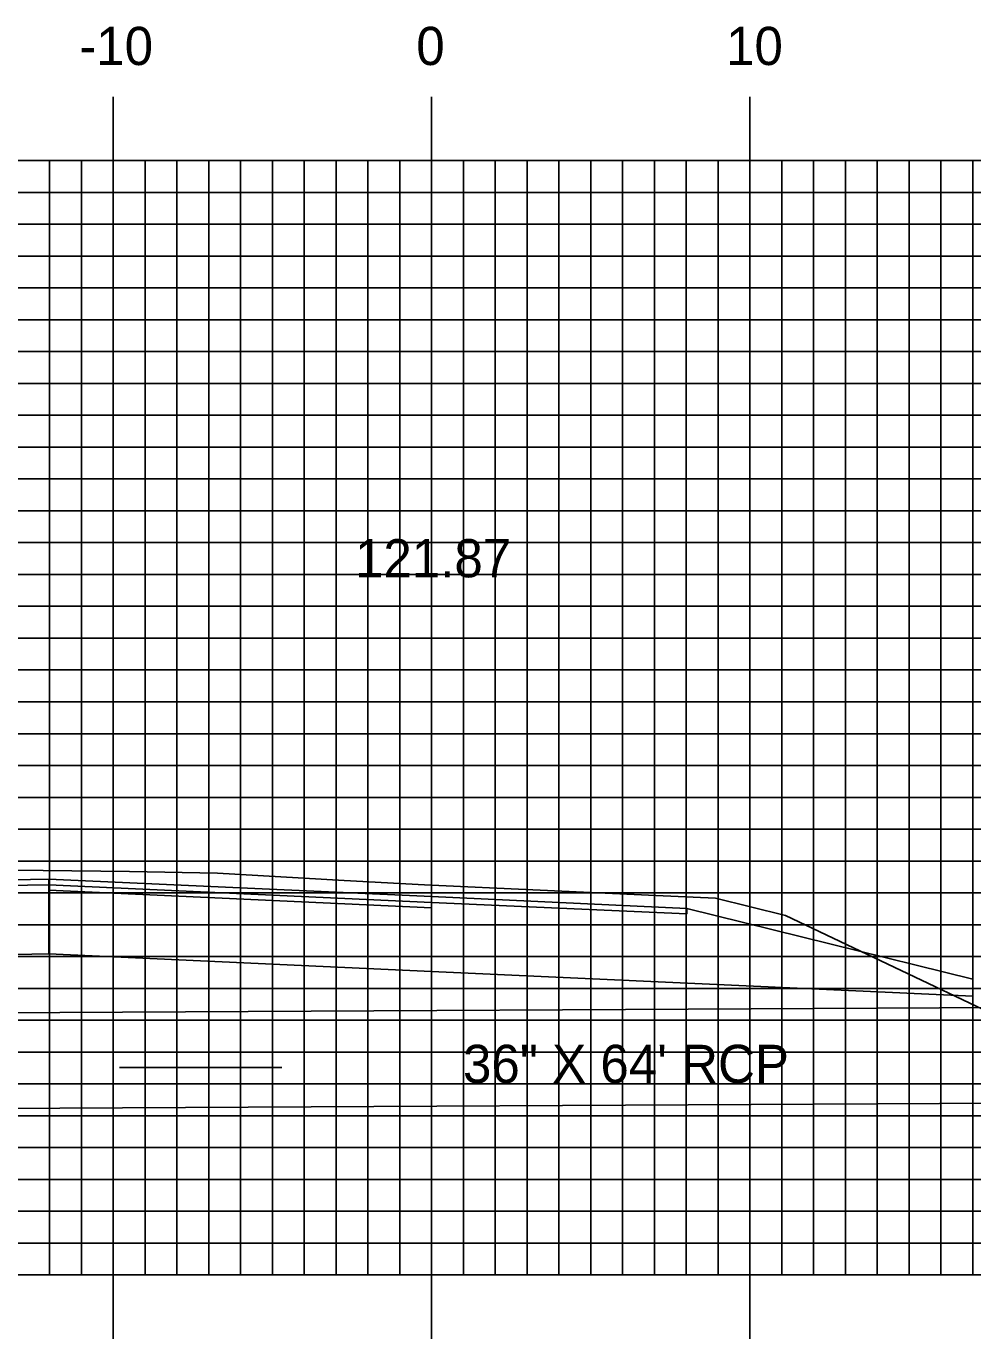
# Model space of a CAD drawing. Extents: x 853328 to 853671, y 364661 to 364881.
# Drawn here: x 853480.56 to 853510.3, y 364684.37 to 364725.59 of the extents above; entities that cross this region are included whole.
import ezdxf

# ---------------------------------------------------------------- set-up
doc = ezdxf.new("R2010")
doc.units = 0
for name, color, linetype in [('D_Drainage_Culvert', 7, 'Continuous'), ('D_Drainage_Text', 7, 'Continuous'), ('D_Roadway_Centerline_Text', 7, 'Continuous'), ('D_Roadway_Edge_Shoulder', 7, 'Continuous'), ('D_Roadway_Edge_TW', 7, 'Continuous'), ('D_Roadway_Pavement', 7, 'Continuous'), ('D_Roadway_SlopeLines', 7, 'Continuous'), ('D_Roadway_SubGrade', 7, 'Continuous'), ('H_V ANNOTATION', 7, 'Continuous'), ('MAJOR', 7, 'Continuous'), ('MINOR', 7, 'Continuous'), ('S_Roadway_Centerline', 7, 'Continuous')]:
    doc.layers.add(name, color=color, linetype=linetype)

msp = doc.modelspace()

# ---------------------------------------------------------------- linework, layer by layer
at = {"layer": 'D_Drainage_Culvert'}
for p, q in [((853457.848, 364694.502), (853517.997, 364694.803)), ((853488.593, 364692.893), (853483.484, 364692.893)), ((853457.863, 364691.494), (853517.992, 364691.803))]:
    msp.add_line(p, q, dxfattribs=at)
at = {"layer": 'D_Roadway_Edge_Shoulder'}
for points in [[(853481.266, 364698.809), (853477.256, 364698.73), (853477.256, 364698.564), (853481.266, 364698.63)], [(853493.294, 364698.255), (853501.313, 364697.886), (853501.313, 364697.719), (853493.294, 364698.075)]]:
    msp.add_lwpolyline(points, close=True, dxfattribs=at)
at = {"layer": 'D_Roadway_Edge_TW'}
msp.add_lwpolyline([(853481.266, 364698.809), (853493.294, 364698.255), (853493.294, 364698.075), (853481.266, 364698.63)], close=True, dxfattribs=at)
at = {"layer": 'D_Roadway_Pavement'}
msp.add_lwpolyline([(853481.266, 364698.63), (853493.294, 364698.075), (853493.294, 364697.909), (853481.266, 364698.463)], close=True, dxfattribs=at)
for points in [[(853481.266, 364698.63), (853481.266, 364698.463)], [(853493.294, 364698.075), (853493.294, 364697.909)], [(853493.294, 364698.075), (853493.294, 364697.909)]]:
    msp.add_lwpolyline(points, dxfattribs=at)
at = {"layer": 'D_Roadway_SlopeLines'}
msp.add_line((853501.313, 364697.886), (853510.296, 364695.661), dxfattribs=at)
at = {"layer": 'D_Roadway_SubGrade'}
for points in [[(853481.266, 364696.463), (853467.26, 364696.186), (853477.256, 364698.73), (853477.256, 364698.564), (853481.266, 364698.63), (853481.266, 364698.463)], [(853481.266, 364698.463), (853493.294, 364697.909), (853493.294, 364695.909), (853481.266, 364696.463)], [(853493.294, 364697.909), (853493.294, 364698.075), (853501.313, 364697.719), (853501.313, 364697.886), (853510.296, 364695.661), (853510.296, 364695.125), (853493.294, 364695.909)]]:
    msp.add_lwpolyline(points, close=True, dxfattribs=at)
at = {"layer": 'MAJOR'}
for p, q in [((853483.294, 364723.378), (853483.294, 364721.374)), ((853493.294, 364723.378), (853493.294, 364721.374)), ((853503.294, 364723.378), (853503.294, 364721.374)), ((853353.294, 364721.374), (853633.294, 364721.374)), ((853353.294, 364721.374), (853633.294, 364721.374)), ((853483.294, 364686.374), (853483.294, 364721.374)), ((853493.294, 364686.374), (853493.294, 364721.374)), ((853503.294, 364686.374), (853503.294, 364721.374)), ((853353.294, 364716.374), (853633.294, 364716.374)), ((853353.294, 364711.374), (853633.294, 364711.374)), ((853353.294, 364706.374), (853633.294, 364706.374)), ((853353.294, 364701.374), (853633.294, 364701.374)), ((853353.294, 364696.374), (853633.294, 364696.374)), ((853353.294, 364691.374), (853633.294, 364691.374)), ((853353.294, 364686.374), (853633.294, 364686.374)), ((853353.294, 364686.374), (853633.294, 364686.374)), ((853483.294, 364684.37), (853483.294, 364686.374)), ((853493.294, 364684.37), (853493.294, 364686.374)), ((853503.294, 364684.37), (853503.294, 364686.374))]:
    msp.add_line(p, q, dxfattribs=at)
at = {"layer": 'MINOR'}
for p, q in [((853481.294, 364686.374), (853481.294, 364721.374)), ((853482.294, 364686.374), (853482.294, 364721.374)), ((853484.294, 364686.374), (853484.294, 364721.374)), ((853485.294, 364686.374), (853485.294, 364721.374)), ((853486.294, 364686.374), (853486.294, 364721.374)), ((853487.294, 364686.374), (853487.294, 364721.374)), ((853488.294, 364686.374), (853488.294, 364721.374)), ((853489.294, 364686.374), (853489.294, 364721.374)), ((853490.294, 364686.374), (853490.294, 364721.374)), ((853491.294, 364686.374), (853491.294, 364721.374)), ((853492.294, 364686.374), (853492.294, 364721.374)), ((853494.294, 364686.374), (853494.294, 364721.374)), ((853495.294, 364686.374), (853495.294, 364721.374)), ((853496.294, 364686.374), (853496.294, 364721.374)), ((853497.294, 364686.374), (853497.294, 364721.374)), ((853498.294, 364686.374), (853498.294, 364721.374)), ((853499.294, 364686.374), (853499.294, 364721.374)), ((853500.294, 364686.374), (853500.294, 364721.374)), ((853501.294, 364686.374), (853501.294, 364721.374)), ((853502.294, 364686.374), (853502.294, 364721.374)), ((853504.294, 364686.374), (853504.294, 364721.374)), ((853505.294, 364686.374), (853505.294, 364721.374)), ((853506.294, 364686.374), (853506.294, 364721.374)), ((853507.294, 364686.374), (853507.294, 364721.374)), ((853508.294, 364686.374), (853508.294, 364721.374)), ((853509.294, 364686.374), (853509.294, 364721.374)), ((853510.294, 364686.374), (853510.294, 364721.374)), ((853353.294, 364720.374), (853633.294, 364720.374)), ((853353.294, 364719.374), (853633.294, 364719.374)), ((853353.294, 364718.374), (853633.294, 364718.374)), ((853353.294, 364717.374), (853633.294, 364717.374)), ((853353.294, 364715.374), (853633.294, 364715.374)), ((853353.294, 364714.374), (853633.294, 364714.374)), ((853353.294, 364713.374), (853633.294, 364713.374)), ((853353.294, 364712.374), (853633.294, 364712.374)), ((853353.294, 364710.374), (853633.294, 364710.374)), ((853353.294, 364709.374), (853633.294, 364709.374)), ((853353.294, 364708.374), (853633.294, 364708.374)), ((853353.294, 364707.374), (853633.294, 364707.374)), ((853353.294, 364705.374), (853633.294, 364705.374)), ((853353.294, 364704.374), (853633.294, 364704.374)), ((853353.294, 364703.374), (853633.294, 364703.374)), ((853353.294, 364702.374), (853633.294, 364702.374)), ((853353.294, 364700.374), (853633.294, 364700.374)), ((853353.294, 364699.374), (853633.294, 364699.374)), ((853353.294, 364698.374), (853633.294, 364698.374)), ((853353.294, 364697.374), (853633.294, 364697.374)), ((853353.294, 364695.374), (853633.294, 364695.374)), ((853353.294, 364694.374), (853633.294, 364694.374)), ((853353.294, 364693.374), (853633.294, 364693.374)), ((853353.294, 364692.374), (853633.294, 364692.374)), ((853353.294, 364690.374), (853633.294, 364690.374)), ((853353.294, 364689.374), (853633.294, 364689.374)), ((853353.294, 364688.374), (853633.294, 364688.374)), ((853353.294, 364687.374), (853633.294, 364687.374))]:
    msp.add_line(p, q, dxfattribs=at)
at = {"layer": 'S_Roadway_Centerline'}
msp.add_lwpolyline([(853477.467, 364699.114), (853483.807, 364699.043), (853486.568, 364698.991), (853490.546, 364698.767), (853493.069, 364698.629), (853500.342, 364698.293), (853502.211, 364698.204), (853504.411, 364697.662), (853514.458, 364692.889)], dxfattribs=at)

# ---------------------------------------------------------------- texts
at = {"layer": 'D_Drainage_Text'}
msp.add_text('36" X 64\' RCP', height=1.2, dxfattribs=at).set_placement((853494.28, 364692.403))
at = {"layer": 'D_Roadway_Centerline_Text'}
msp.add_text('121.87', height=1.2, dxfattribs=at).set_placement((853490.887, 364708.285))
at = {"layer": 'H_V ANNOTATION'}
for s, p in [('-10', (853482.224, 364724.374)), ('0', (853492.813, 364724.374)), ('10', (853502.545, 364724.374))]:
    msp.add_text(s, height=1.2, dxfattribs=at).set_placement(p)

doc.saveas('drawing.dxf')
